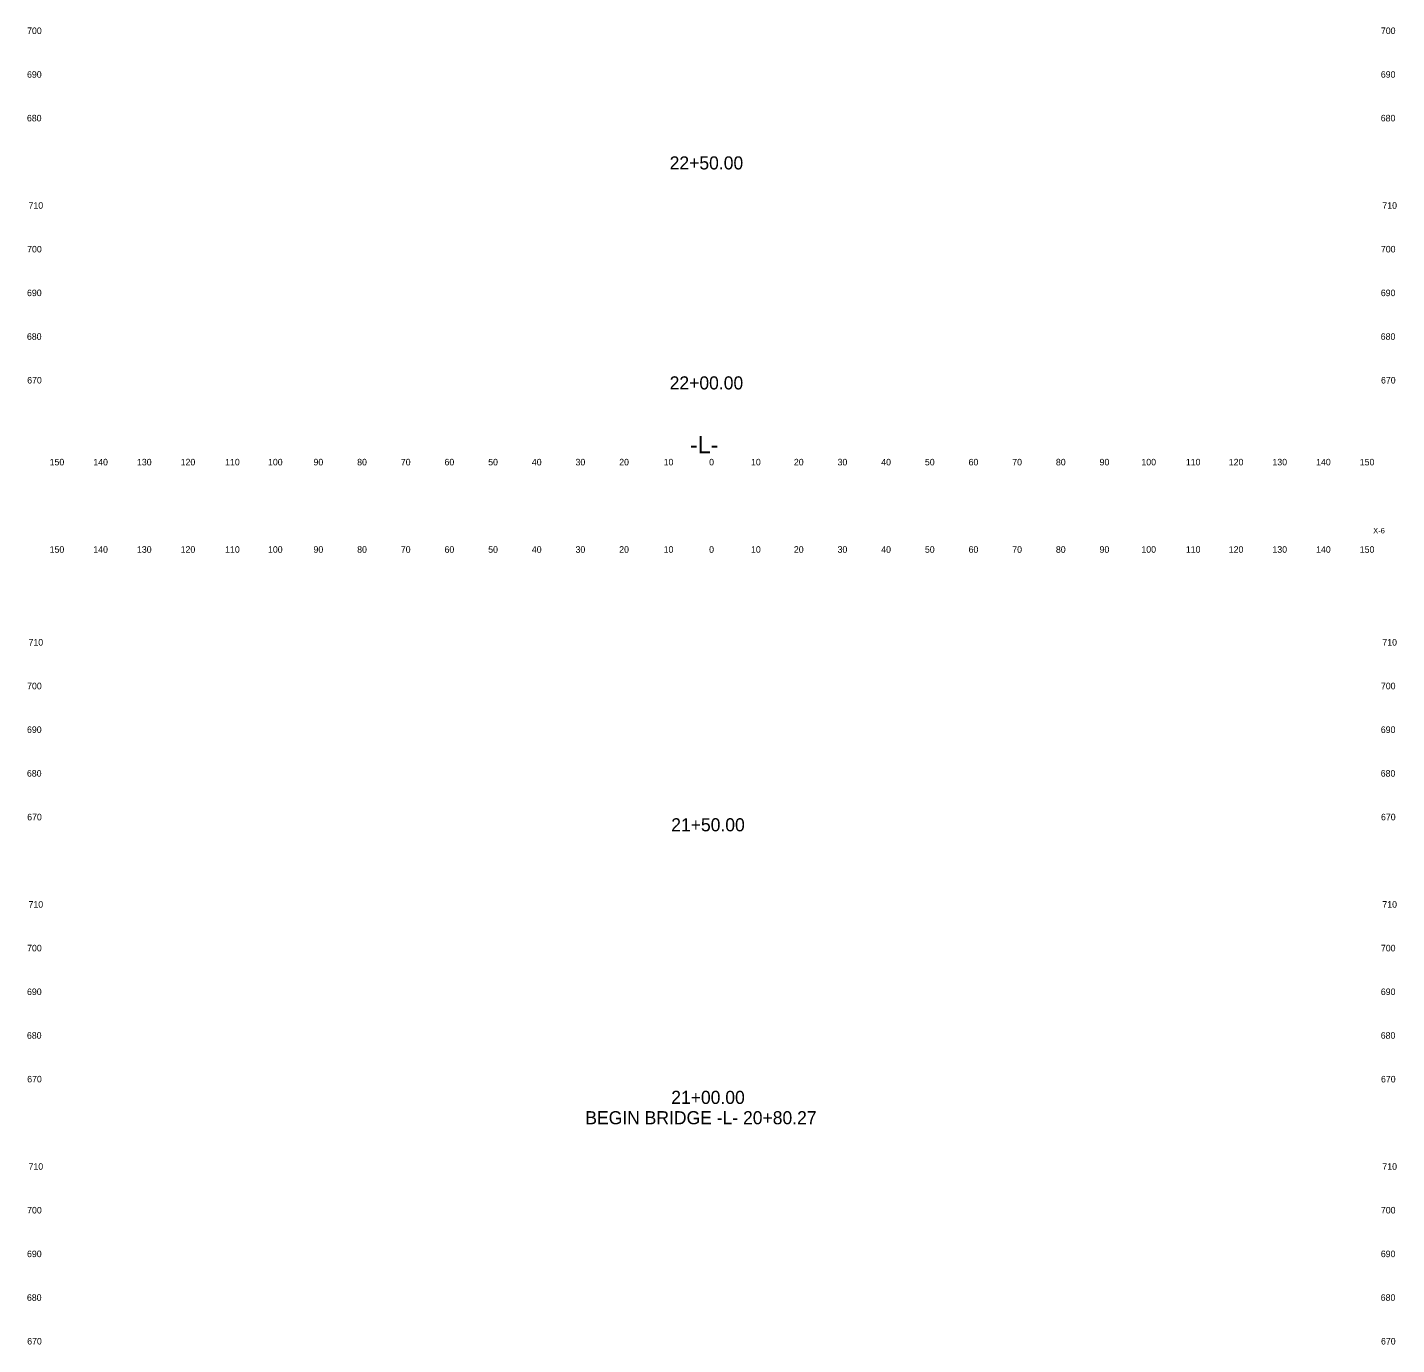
# Model space of a CAD drawing. Extents: x 3 to 317, y 0 to 2407.
# Drawn here: x 3.3 to 316.9, y 900 to 1201.5 of the extents above; entities that cross this region are included whole.
import ezdxf

# ---------------------------------------------------------------- set-up
doc = ezdxf.new("R2010")
doc.units = 0
for name, color, linetype in [('Prop XS Ditch Standard Text', 7, 'Continuous'), ('Prop XS Dump Level', 7, 'Continuous'), ('Prop XS SE Text', 7, 'Continuous'), ('Prop XS Sheet Number', 7, 'Continuous'), ('Prop XS SS Elevation Text', 7, 'Continuous')]:
    doc.layers.add(name, color=color, linetype=linetype)

msp = doc.modelspace()

# ---------------------------------------------------------------- texts
at = {"layer": 'Prop XS Ditch Standard Text'}
for s, p in [('22+50.00', (150.41, 1169)), ('22+00.00', (150.41, 1118.64)), ('21+50.00', (150.77, 1017.48)), ('21+00.00', (150.77, 955.08)), ('BEGIN BRIDGE -L- 20+80.27', (131.1, 950.42))]:
    msp.add_text(s, height=3, dxfattribs=at).set_placement(p)
at = {"layer": 'Prop XS Dump Level'}
for s, p in [('150', (8.44, 1101.25)), ('140', (18.44, 1101.25)), ('130', (28.44, 1101.25)), ('120', (38.44, 1101.25)), ('110', (48.62, 1101.25)), ('100', (58.44, 1101.25)), ('90', (68.86, 1101.25)), ('80', (78.86, 1101.25)), ('70', (88.86, 1101.25)), ('60', (98.86, 1101.25)), ('50', (108.86, 1101.25)), ('40', (118.86, 1101.25)), ('30', (128.86, 1101.25)), ('20', (138.86, 1101.25)), ('10', (149.04, 1101.25)), ('0', (159.45, 1101.25)), ('10', (169.04, 1101.25)), ('20', (178.86, 1101.25)), ('30', (188.86, 1101.25)), ('40', (198.86, 1101.25)), ('50', (208.86, 1101.25)), ('60', (218.86, 1101.25)), ('70', (228.86, 1101.25)), ('80', (238.86, 1101.25)), ('90', (248.86, 1101.25)), ('100', (258.44, 1101.25)), ('110', (268.62, 1101.25)), ('120', (278.44, 1101.25)), ('130', (288.44, 1101.25)), ('140', (298.44, 1101.25)), ('150', (308.44, 1101.25)), ('150', (8.44, 1081.25)), ('140', (18.44, 1081.25)), ('130', (28.44, 1081.25)), ('120', (38.44, 1081.25)), ('110', (48.62, 1081.25)), ('100', (58.44, 1081.25)), ('90', (68.86, 1081.25)), ('80', (78.86, 1081.25)), ('70', (88.86, 1081.25)), ('60', (98.86, 1081.25)), ('50', (108.86, 1081.25)), ('40', (118.86, 1081.25)), ('30', (128.86, 1081.25)), ('20', (138.86, 1081.25)), ('10', (149.04, 1081.25)), ('0', (159.45, 1081.25)), ('10', (169.04, 1081.25)), ('20', (178.86, 1081.25)), ('30', (188.86, 1081.25)), ('40', (198.86, 1081.25)), ('50', (208.86, 1081.25)), ('60', (218.86, 1081.25)), ('70', (228.86, 1081.25)), ('80', (238.86, 1081.25)), ('90', (248.86, 1081.25)), ('100', (258.44, 1081.25)), ('110', (268.62, 1081.25)), ('120', (278.44, 1081.25)), ('130', (288.44, 1081.25)), ('140', (298.44, 1081.25)), ('150', (308.44, 1081.25))]:
    msp.add_text(s, height=1.5, dxfattribs=at).set_placement(p)
at = {"layer": 'Prop XS SE Text'}
for s, p in [('700', (3.28, 1200)), ('700', (313.28, 1200)), ('690', (3.26, 1190)), ('690', (313.26, 1190)), ('680', (3.24, 1180)), ('680', (313.24, 1180)), ('710', (3.61, 1160)), ('710', (313.61, 1160)), ('700', (3.28, 1150)), ('700', (313.28, 1150)), ('690', (3.26, 1140)), ('690', (313.26, 1140)), ('680', (3.24, 1130)), ('680', (313.24, 1130)), ('670', (3.3, 1120)), ('670', (313.3, 1120)), ('710', (3.61, 1060)), ('710', (313.61, 1060)), ('700', (3.28, 1050)), ('700', (313.28, 1050)), ('690', (3.26, 1040)), ('690', (313.26, 1040)), ('680', (3.24, 1030)), ('680', (313.24, 1030)), ('670', (3.3, 1020)), ('670', (313.3, 1020)), ('710', (3.61, 1000)), ('710', (313.61, 1000)), ('700', (3.28, 990)), ('700', (313.28, 990)), ('690', (3.26, 980)), ('690', (313.26, 980)), ('680', (3.24, 970)), ('680', (313.24, 970)), ('670', (3.3, 960)), ('670', (313.3, 960)), ('710', (3.61, 940)), ('710', (313.61, 940)), ('700', (3.28, 930)), ('700', (313.28, 930)), ('690', (3.26, 920)), ('690', (313.26, 920)), ('680', (3.24, 910)), ('680', (313.24, 910)), ('670', (3.3, 900)), ('670', (313.3, 900))]:
    msp.add_text(s, height=1.5, dxfattribs=at).set_placement(p)
at = {"layer": 'Prop XS Sheet Number'}
msp.add_text('X-6', height=1.25, dxfattribs=at).set_placement((311.5, 1085.69))
at = {"layer": 'Prop XS SS Elevation Text'}
msp.add_text('-L-', height=4, dxfattribs=at).set_placement((155.06, 1104))

doc.saveas('drawing.dxf')
